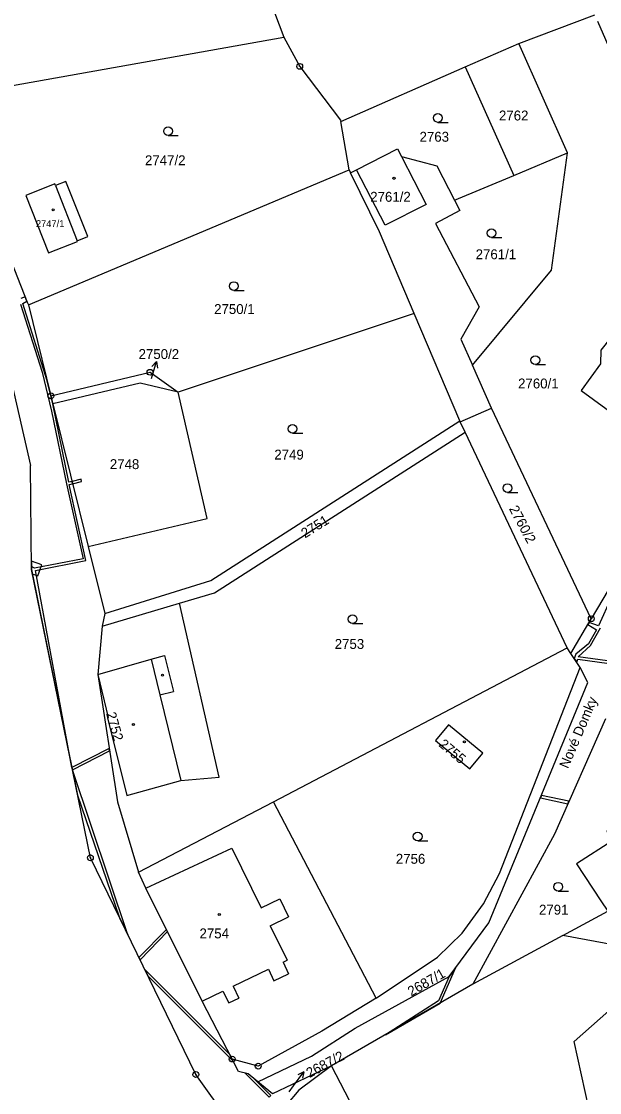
# Model space of a CAD drawing. Extents: x -562167 to -556918, y -1077891 to -1070763.
# Drawn here: x -561895.9 to -561796.8, y -1076447.3 to -1076263.5 of the extents above; entities that cross this region are included whole.
import ezdxf

# ---------------------------------------------------------------- set-up
doc = ezdxf.new("R2010")
doc.units = 0
for name, color, linetype in [('Hranice parcel', 7, 'Continuous'), ('Parcelní čísla', 7, 'Continuous'), ('Pop  PČ popisy', 7, 'Continuous'), ('Vnitřní kresba', 7, 'Continuous'), ('Věcná břemena k části', 7, 'Continuous'), ('Značky bodu BP', 7, 'Continuous'), ('Značky budov', 7, 'Continuous'), ('Značky kultur', 7, 'Continuous')]:
    doc.layers.add(name, color=color, linetype=linetype)

msp = doc.modelspace()

# ---------------------------------------------------------------- linework, layer by layer
at = {"layer": 'Hranice parcel'}
for p, q in [((-561861.02, -1076239.17), (-561850.92, -1076266.21)), ((-561810.64, -1076267.31), (-561797.59, -1076262.35)), ((-561797.11, -1076263.45), (-561783.26, -1076295.58)), ((-561908.81, -1076276.5), (-561850.92, -1076266.21)), ((-561819.8, -1076271.31), (-561810.64, -1076267.31)), ((-561802.26, -1076286.02), (-561810.64, -1076267.31)), ((-561841.17, -1076280.65), (-561819.8, -1076271.31)), ((-561819.8, -1076271.31), (-561811.48, -1076289.91)), ((-561839.72, -1076288.98), (-561841.17, -1076280.65)), ((-561811.48, -1076289.91), (-561802.26, -1076286.02)), ((-561824.71, -1076288.25), (-561821.64, -1076294.19)), ((-561894.74, -1076312.15), (-561839.72, -1076288.98)), ((-561839.72, -1076288.98), (-561839.47, -1076289.5)), ((-561839.47, -1076289.5), (-561838.45, -1076288.97)), ((-561821.64, -1076294.19), (-561811.48, -1076289.91)), ((-561821.64, -1076294.19), (-561820.74, -1076295.93)), ((-561894.74, -1076312.15), (-561890.88, -1076327.75)), ((-561828.57, -1076313.61), (-561869.04, -1076327.09)), ((-561820.75, -1076332.02), (-561828.57, -1076313.61)), ((-561820.55, -1076318.03), (-561818.58, -1076322.46)), ((-561815.29, -1076329.83), (-561818.58, -1076322.46)), ((-561890.88, -1076327.75), (-561890.55, -1076329.1)), ((-561890.55, -1076329.1), (-561884.49, -1076353.57)), ((-561820.67, -1076332.2), (-561815.29, -1076329.83)), ((-561798.19, -1076365.98), (-561815.29, -1076329.83)), ((-561820.67, -1076332.2), (-561820.75, -1076332.02)), ((-561819.81, -1076334), (-561820.67, -1076332.2)), ((-561802.32, -1076371), (-561819.81, -1076334)), ((-561894.22, -1076357.54), (-561894.35, -1076339.72)), ((-561884.49, -1076353.57), (-561881.64, -1076365.06)), ((-561882.06, -1076367.27), (-561868.84, -1076363.32)), ((-561881.64, -1076365.06), (-561882.06, -1076367.27)), ((-561882.06, -1076367.27), (-561882.85, -1076375.55)), ((-561801.7, -1076371.93), (-561798.19, -1076365.98)), ((-561852.72, -1076397.39), (-561802.32, -1076371)), ((-561801.7, -1076371.93), (-561802.32, -1076371)), ((-561800.1, -1076374.35), (-561801.7, -1076371.93)), ((-561875.85, -1076409.49), (-561852.72, -1076397.39)), ((-561835.08, -1076431.11), (-561852.72, -1076397.39)), ((-561803.06, -1076420.33), (-561795.34, -1076416.14)), ((-561803.06, -1076420.33), (-561818.5, -1076428.71)), ((-561793.53, -1076422.12), (-561803.06, -1076420.33)), ((-561818.5, -1076428.71), (-561842.76, -1076442.71)), ((-561842.76, -1076442.71), (-561852.86, -1076447.49)), ((-561852.86, -1076447.49), (-561855.36, -1076445.45))]:
    msp.add_line(p, q, dxfattribs=at)
for points in [[(-561941.57, -1076177.17), (-561930.91, -1076210.27), (-561917.39, -1076257.18), (-561903.13, -1076301.58), (-561894.35, -1076339.72)], [(-561850.92, -1076266.21), (-561848.2, -1076271.21), (-561841.2, -1076280.45), (-561841.17, -1076280.65)], [(-561908.81, -1076276.5), (-561894.95, -1076311.64), (-561894.74, -1076312.15)], [(-561838.45, -1076288.97), (-561831.41, -1076285.36), (-561830.73, -1076286.68), (-561824.71, -1076288.25)], [(-561818.58, -1076322.46), (-561805.01, -1076306.2), (-561802.26, -1076286.02)], [(-561828.57, -1076313.61), (-561834.51, -1076299.62), (-561839.47, -1076289.5)], [(-561886.32, -1076301.27), (-561886.37, -1076301.15), (-561884.55, -1076300.41), (-561888.31, -1076290.96), (-561890.09, -1076291.66), (-561890.2, -1076291.39), (-561895.19, -1076293.36), (-561891.27, -1076303.23), (-561886.32, -1076301.27)], [(-561820.74, -1076295.93), (-561824.94, -1076298.14), (-561817.41, -1076312.48), (-561820.55, -1076318.03)], [(-561776.12, -1076329.48), (-561775.95, -1076329.61), (-561772.9, -1076325.44), (-561772.02, -1076324.21), (-561776.7, -1076320.95), (-561775.07, -1076318.92), (-561779.02, -1076315.8), (-561775.84, -1076311.86), (-561776.57, -1076310.44), (-561780.21, -1076307.64), (-561784.61, -1076304.88), (-561796.54, -1076319.88), (-561796.59, -1076322.27), (-561799.94, -1076326.84), (-561791.44, -1076333.01)], [(-561890.88, -1076327.75), (-561873.88, -1076323.7), (-561869.04, -1076327.09)], [(-561869.04, -1076327.09), (-561875.55, -1076325.55), (-561890.55, -1076329.1)], [(-561884.49, -1076353.57), (-561864.06, -1076348.79), (-561869.04, -1076327.09)], [(-561768.71, -1076326.62), (-561773.4, -1076333.37), (-561793.3, -1076357.69), (-561798.19, -1076365.98)], [(-561881.64, -1076365.06), (-561863.47, -1076359.42), (-561820.75, -1076332.02)], [(-561868.84, -1076363.32), (-561862.82, -1076361.52), (-561819.81, -1076334)], [(-561854.5, -1076460.24), (-561866.01, -1076444.2), (-561884.1, -1076407), (-561894.22, -1076357.54)], [(-561882.85, -1076375.55), (-561881.03, -1076382.93), (-561881.17, -1076382.97), (-561877.87, -1076396.34), (-561868.62, -1076393.75), (-561862.01, -1076393.15), (-561868.84, -1076363.32)], [(-561855.36, -1076445.45), (-561846.18, -1076441.02), (-561838.72, -1076436.26), (-561822.57, -1076427.38), (-561815.77, -1076418.19), (-561798.78, -1076376.91), (-561800.1, -1076374.35)], [(-561835.08, -1076431.11), (-561824.58, -1076424.08), (-561820.34, -1076419.96), (-561816.68, -1076414.91), (-561813.95, -1076409.69), (-561800.1, -1076374.35)], [(-561882.85, -1076375.55), (-561879.44, -1076397.38), (-561875.85, -1076409.49)], [(-561816.8, -1076389.04), (-561822.69, -1076384.19), (-561824.92, -1076386.89), (-561819.03, -1076391.74), (-561816.8, -1076389.04)], [(-561795.73, -1076383.18), (-561804.53, -1076402.93), (-561818.5, -1076428.71)], [(-561788.37, -1076400), (-561790.08, -1076401.13), (-561791.06, -1076399.57), (-561795.51, -1076402.45), (-561794.5, -1076404.05), (-561800.75, -1076408.03), (-561796.56, -1076414.38), (-561795.34, -1076416.14)], [(-561859.78, -1076441.54), (-561864.94, -1076431.58), (-561874.57, -1076412.19), (-561875.85, -1076409.49)], [(-561795.36, -1076464.75), (-561796.11, -1076461.39), (-561801.13, -1076438.55), (-561791.22, -1076429.79), (-561793.53, -1076422.12)], [(-561835.08, -1076431.11), (-561844.43, -1076436.78), (-561855.32, -1076442.75), (-561859.78, -1076441.54)], [(-561855.36, -1076445.45), (-561857.05, -1076444.08), (-561858.68, -1076443.67), (-561859.78, -1076441.54)], [(-561842.76, -1076442.71), (-561848.38, -1076446.86), (-561850.49, -1076449.42)], [(-561834, -1076478.84), (-561822.64, -1076462.9), (-561826.57, -1076459.82), (-561838.85, -1076450.2), (-561842.76, -1076442.71)]]:
    msp.add_lwpolyline(points, dxfattribs=at)
at = {"layer": 'Pop  PČ popisy'}
for p, q in [((-561873.62, -1076324.75), (-561872.79, -1076321.86)), ((-561872.79, -1076321.86), (-561873.55, -1076322.69)), ((-561872.79, -1076321.86), (-561872.59, -1076322.97)), ((-561849.28, -1076446.16), (-561847.52, -1076443.73)), ((-561847.52, -1076443.73), (-561848.51, -1076444.25)), ((-561847.52, -1076443.73), (-561847.7, -1076444.84)), ((-561850.01, -1076447.18), (-561849.28, -1076446.16))]:
    msp.add_line(p, q, dxfattribs=at)
at = {"layer": 'Vnitřní kresba'}
for p, q in [((-561830.73, -1076286.68), (-561826.5, -1076294.89)), ((-561833.52, -1076298.48), (-561838.45, -1076288.97)), ((-561890.09, -1076291.66), (-561886.37, -1076301.15)), ((-561826.5, -1076294.89), (-561833.52, -1076298.48)), ((-561882.85, -1076375.55), (-561873.69, -1076372.95)), ((-561873.69, -1076372.95), (-561871.38, -1076372.3)), ((-561873.69, -1076372.95), (-561872.22, -1076379.06)), ((-561871.38, -1076372.3), (-561869.86, -1076378.49)), ((-561872.22, -1076379.06), (-561869.86, -1076378.49)), ((-561872.22, -1076379.06), (-561868.62, -1076393.75)), ((-561874.57, -1076412.19), (-561859.87, -1076405.38)), ((-561859.87, -1076405.38), (-561854.82, -1076415.57)), ((-561854.82, -1076415.57), (-561851.64, -1076414.03)), ((-561851.64, -1076414.03), (-561850.15, -1076417.11)), ((-561853.28, -1076418.68), (-561850.15, -1076417.11)), ((-561853.28, -1076418.68), (-561850.34, -1076424.59)), ((-561851.04, -1076424.93), (-561850.34, -1076424.59)), ((-561859.63, -1076429.04), (-561853.58, -1076426.14)), ((-561853.58, -1076426.14), (-561852.63, -1076428.13)), ((-561851.04, -1076424.93), (-561850.12, -1076426.91)), ((-561852.63, -1076428.13), (-561850.12, -1076426.91)), ((-561864.94, -1076431.58), (-561861.38, -1076429.88)), ((-561861.38, -1076429.88), (-561860.38, -1076431.91)), ((-561859.63, -1076429.04), (-561858.64, -1076431.07)), ((-561860.38, -1076431.91), (-561858.64, -1076431.07))]:
    msp.add_line(p, q, dxfattribs=at)
at = {"layer": 'Věcná břemena k části'}
for points in [[(-561896.08, -1076312.02), (-561892.4, -1076323.7), (-561890.78, -1076330.35), (-561888.18, -1076342.82), (-561885.35, -1076355.7), (-561893.71, -1076357.32), (-561894.22, -1076357), (-561894.22, -1076357.54), (-561892.02, -1076368.29), (-561887.27, -1076391.49), (-561893.52, -1076357.69), (-561884.87, -1076356.02), (-561887.73, -1076342.97), (-561887.15, -1076342.82), (-561887.25, -1076342.43), (-561887.82, -1076342.58), (-561890.55, -1076329.1), (-561891.52, -1076325.17), (-561895.7, -1076311.89), (-561895.01, -1076311.48), (-561895.3, -1076310.74), (-561896.01, -1076311.03)], [(-561794.7, -1076362.26), (-561796.93, -1076367.21), (-561798.57, -1076366.62), (-561798.77, -1076366.96), (-561797.28, -1076367.88), (-561798.65, -1076370.31), (-561800.86, -1076372.05), (-561801.12, -1076372.81), (-561800.7, -1076373.44), (-561800.52, -1076372.94), (-561791.79, -1076374.1)], [(-561791.64, -1076373.72), (-561800.46, -1076372.54), (-561798.35, -1076370.57), (-561796.64, -1076367.55)]]:
    msp.add_lwpolyline(points, dxfattribs=at)
for points in [[(-561887.25, -1076342.43), (-561887.15, -1076342.82), (-561885.62, -1076342.41), (-561885.71, -1076342.02)], [(-561894.22, -1076357.54), (-561894.07, -1076358.29), (-561893.09, -1076358.63), (-561892.43, -1076356.74), (-561894.23, -1076356.11)], [(-561880.8, -1076388.66), (-561880.87, -1076388.25), (-561887.27, -1076391.49), (-561887.19, -1076391.9)], [(-561879.17, -1076417.14), (-561877.67, -1076420.22), (-561887.19, -1076391.9), (-561886.3, -1076396.23)], [(-561802.22, -1076397.74), (-561802.02, -1076397.29), (-561806.76, -1076396.31), (-561806.93, -1076396.7)], [(-561870.87, -1076419.65), (-561871.05, -1076419.28), (-561875.78, -1076424.11), (-561875.59, -1076424.49)], [(-561859.58, -1076441.93), (-561860.19, -1076440.76), (-561874.78, -1076426.17), (-561874.24, -1076427.27)], [(-561821.49, -1076425.92), (-561822.57, -1076427.38), (-561824.39, -1076431.55), (-561833.49, -1076437.36), (-561824.13, -1076431.96)], [(-561857.05, -1076444.08), (-561857.56, -1076443.95), (-561853.47, -1076448.05), (-561853.17, -1076447.78), (-561856.09, -1076444.86)]]:
    msp.add_lwpolyline(points, close=True, dxfattribs=at)
at = {"layer": 'Značky bodu BP'}
for centre, radius in [((-561848.2, -1076271.21), 0.5), ((-561848.2, -1076271.21), 0.0303), ((-561873.88, -1076323.7), 0.5), ((-561873.88, -1076323.7), 0.0303), ((-561890.88, -1076327.75), 0.5), ((-561890.88, -1076327.75), 0.0303), ((-561798.19, -1076365.98), 0.5), ((-561798.19, -1076365.98), 0.0303), ((-561884.1, -1076407), 0.5), ((-561884.1, -1076407), 0.0303), ((-561859.78, -1076441.54), 0.5), ((-561859.78, -1076441.54), 0.0303), ((-561855.32, -1076442.75), 0.5), ((-561855.32, -1076442.75), 0.0303), ((-561866.01, -1076444.2), 0.5), ((-561866.01, -1076444.2), 0.0303)]:
    msp.add_circle(centre, radius, dxfattribs=at)
at = {"layer": 'Značky budov'}
for centre in [(-561832.03, -1076290.41), (-561890.5, -1076295.83), (-561871.75, -1076375.65), (-561876.73, -1076384.14), (-561819.96, -1076387.12), (-561861.99, -1076416.74)]:
    msp.add_circle(centre, 0.175, dxfattribs=at)
at = {"layer": 'Značky kultur'}
for p, q in [((-561824.51, -1076280.81), (-561822.76, -1076280.81)), ((-561870.78, -1076283.07), (-561869.03, -1076283.07)), ((-561815.3, -1076300.57), (-561813.55, -1076300.57)), ((-561859.5, -1076309.65), (-561857.75, -1076309.65)), ((-561807.79, -1076322.37), (-561806.04, -1076322.37)), ((-561849.43, -1076334.16), (-561847.68, -1076334.16)), ((-561812.57, -1076344.31), (-561810.82, -1076344.31)), ((-561839.13, -1076366.8), (-561837.38, -1076366.8)), ((-561827.97, -1076404.09), (-561826.22, -1076404.09)), ((-561803.86, -1076412.72), (-561802.11, -1076412.72))]:
    msp.add_line(p, q, dxfattribs=at)
for centre in [(-561824.51, -1076280.06), (-561870.78, -1076282.32), (-561815.3, -1076299.82), (-561859.5, -1076308.9), (-561807.79, -1076321.62), (-561849.43, -1076333.41), (-561812.57, -1076343.56), (-561839.13, -1076366.05), (-561827.97, -1076403.34), (-561803.86, -1076411.97)]:
    msp.add_circle(centre, 0.75, dxfattribs=at)

# ---------------------------------------------------------------- texts
at = {"layer": 'Parcelní čísla'}
for s, height, p in [('2762', 1.7, (-561814.03, -1076280.49)), ('2763', 1.7, (-561827.65, -1076284.14)), ('2747/2', 1.7, (-561874.74, -1076288.17)), ('2761/2', 1.7, (-561836.11, -1076294.44)), ('2747/1', 1.19, (-561893.44, -1076298.79)), ('2761/1', 1.7, (-561818.03, -1076304.3)), ('2750/1', 1.7, (-561862.88, -1076313.7)), ('2750/2', 1.7, (-561875.84, -1076321.42)), ('2760/1', 1.7, (-561810.75, -1076326.47)), ('2749', 1.7, (-561852.56, -1076338.67)), ('2748', 1.7, (-561880.77, -1076340.31)), ('2753', 1.7, (-561842.2, -1076371.16)), ('2756', 1.7, (-561831.72, -1076408.03)), ('2791', 1.7, (-561807.16, -1076416.76)), ('2754', 1.7, (-561865.39, -1076420.83))]:
    msp.add_text(s, height=height, dxfattribs=at).set_placement(p)
for s, rotation, p in [('2760/2', 298, (-561812.36, -1076347.1)), ('2751', 32, (-561847.29, -1076352.22)), ('2752', 286, (-561881.43, -1076382.26)), ('2755', 320, (-561824.48, -1076387.76)), ('2687/1', 30, (-561829.07, -1076430.83)), ('2687/2', 28, (-561846.53, -1076444.81))]:
    msp.add_text(s, height=1.7, rotation=rotation, dxfattribs=at).set_placement(p)
at = {"layer": 'Pop  PČ popisy'}
msp.add_text('Nové Domky', height=1.7, rotation=67, dxfattribs=at).set_placement((-561802.19, -1076391.81))

doc.saveas('drawing.dxf')
